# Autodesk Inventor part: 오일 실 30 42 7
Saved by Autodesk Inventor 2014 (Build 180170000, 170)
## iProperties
Created: 2025-06
Part Number: 오일 실 30 42 7
Material: 일반
Document SubType Name: Modeling
Designer: dg
Density: 1 g/cm^3
Appearance: 기본값
Author: dg
Author: jhkim
Description: 오일 실 - 스프링 장착, 금속 케이스 SM
Creation Date: 2025-05-23
Sending System: Autodesk Inventor 2026
Preprocessor: ST-DEVELOPER v20.1
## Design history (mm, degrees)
node "오일 실 30 42 71"
body "Solid1"
node "기준1"
